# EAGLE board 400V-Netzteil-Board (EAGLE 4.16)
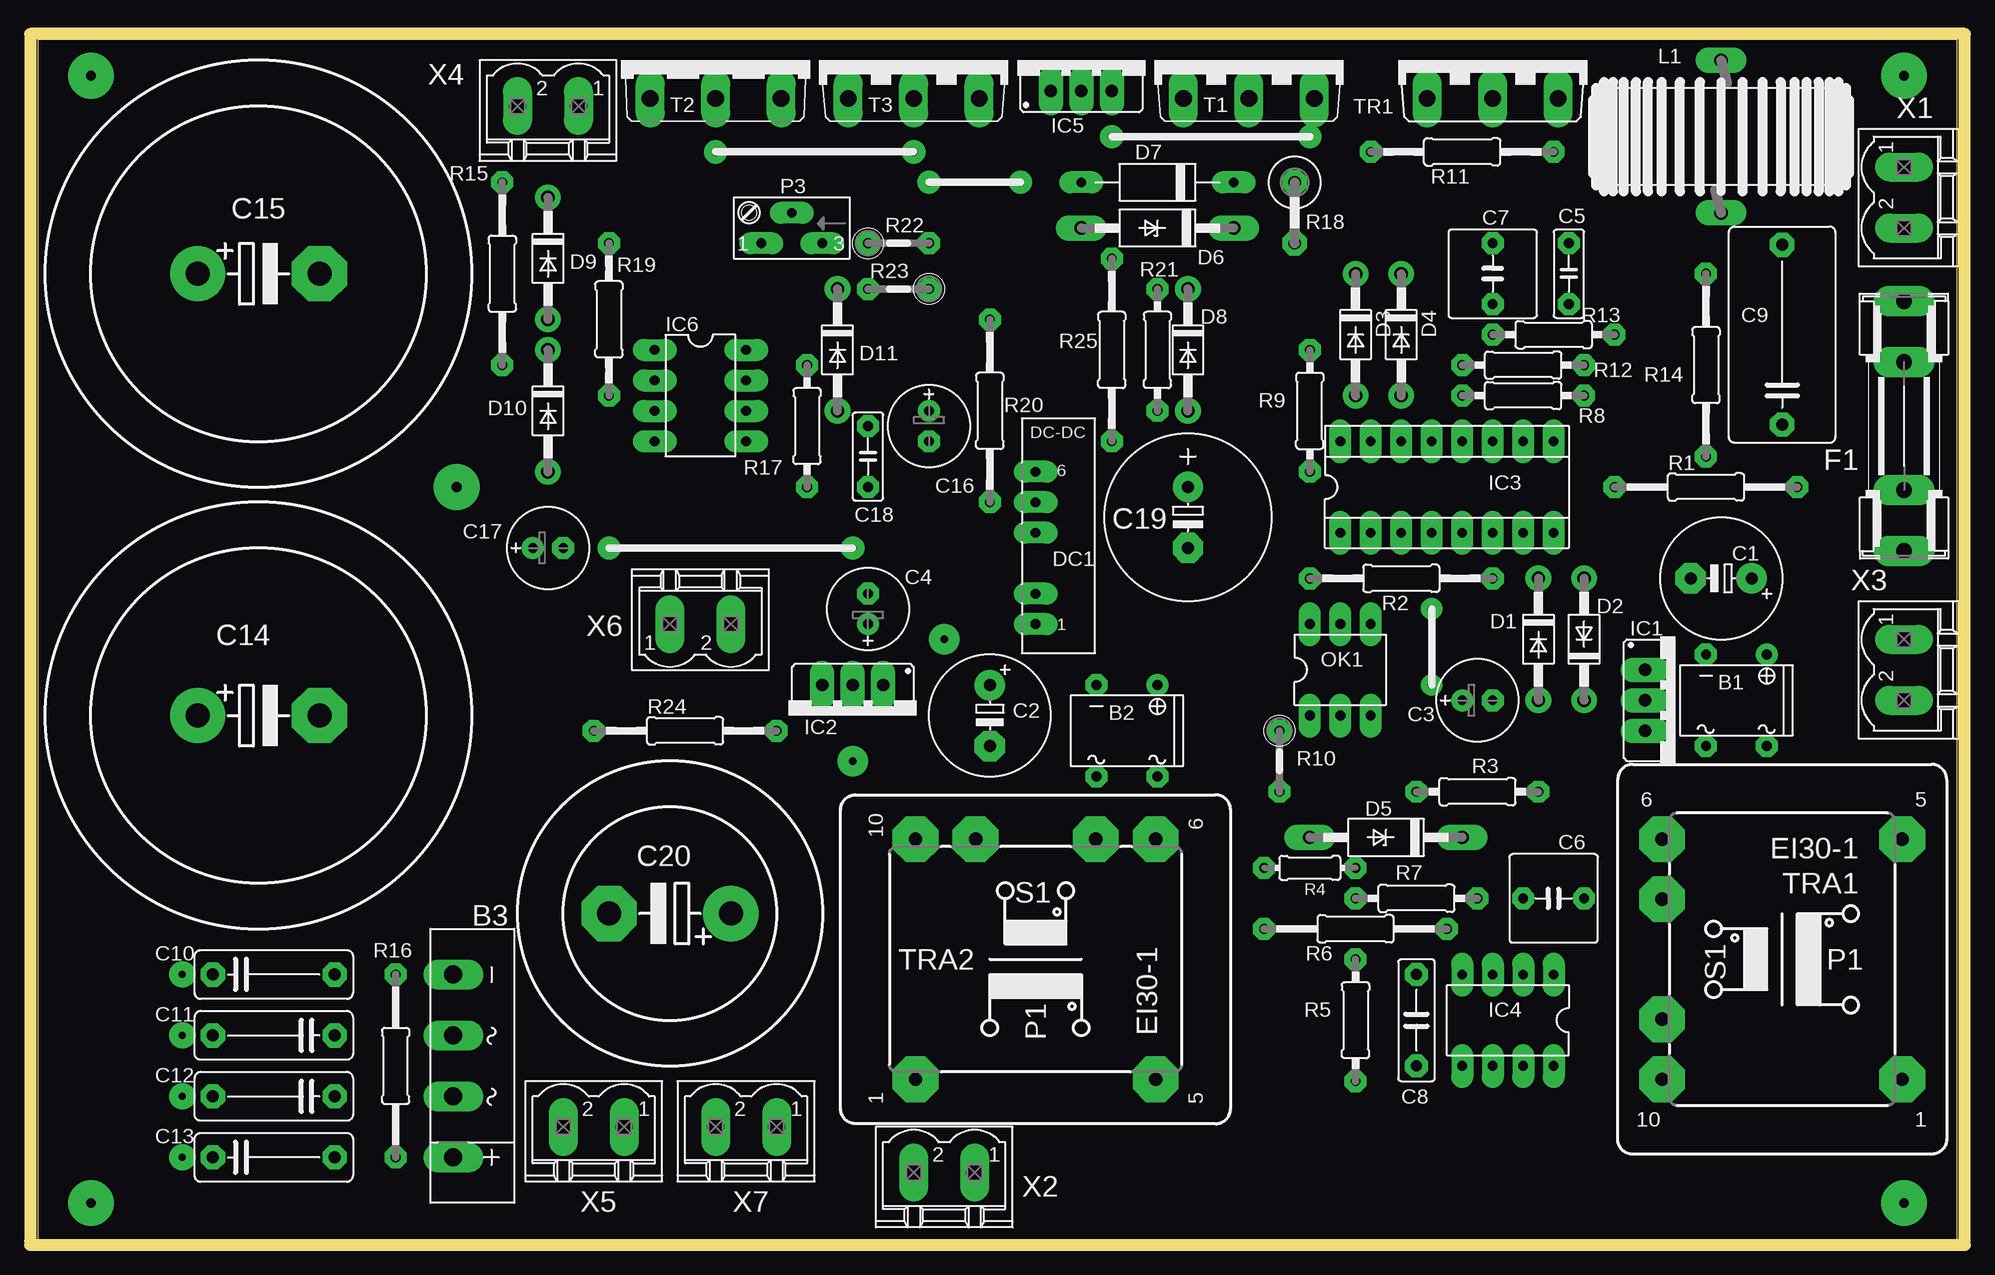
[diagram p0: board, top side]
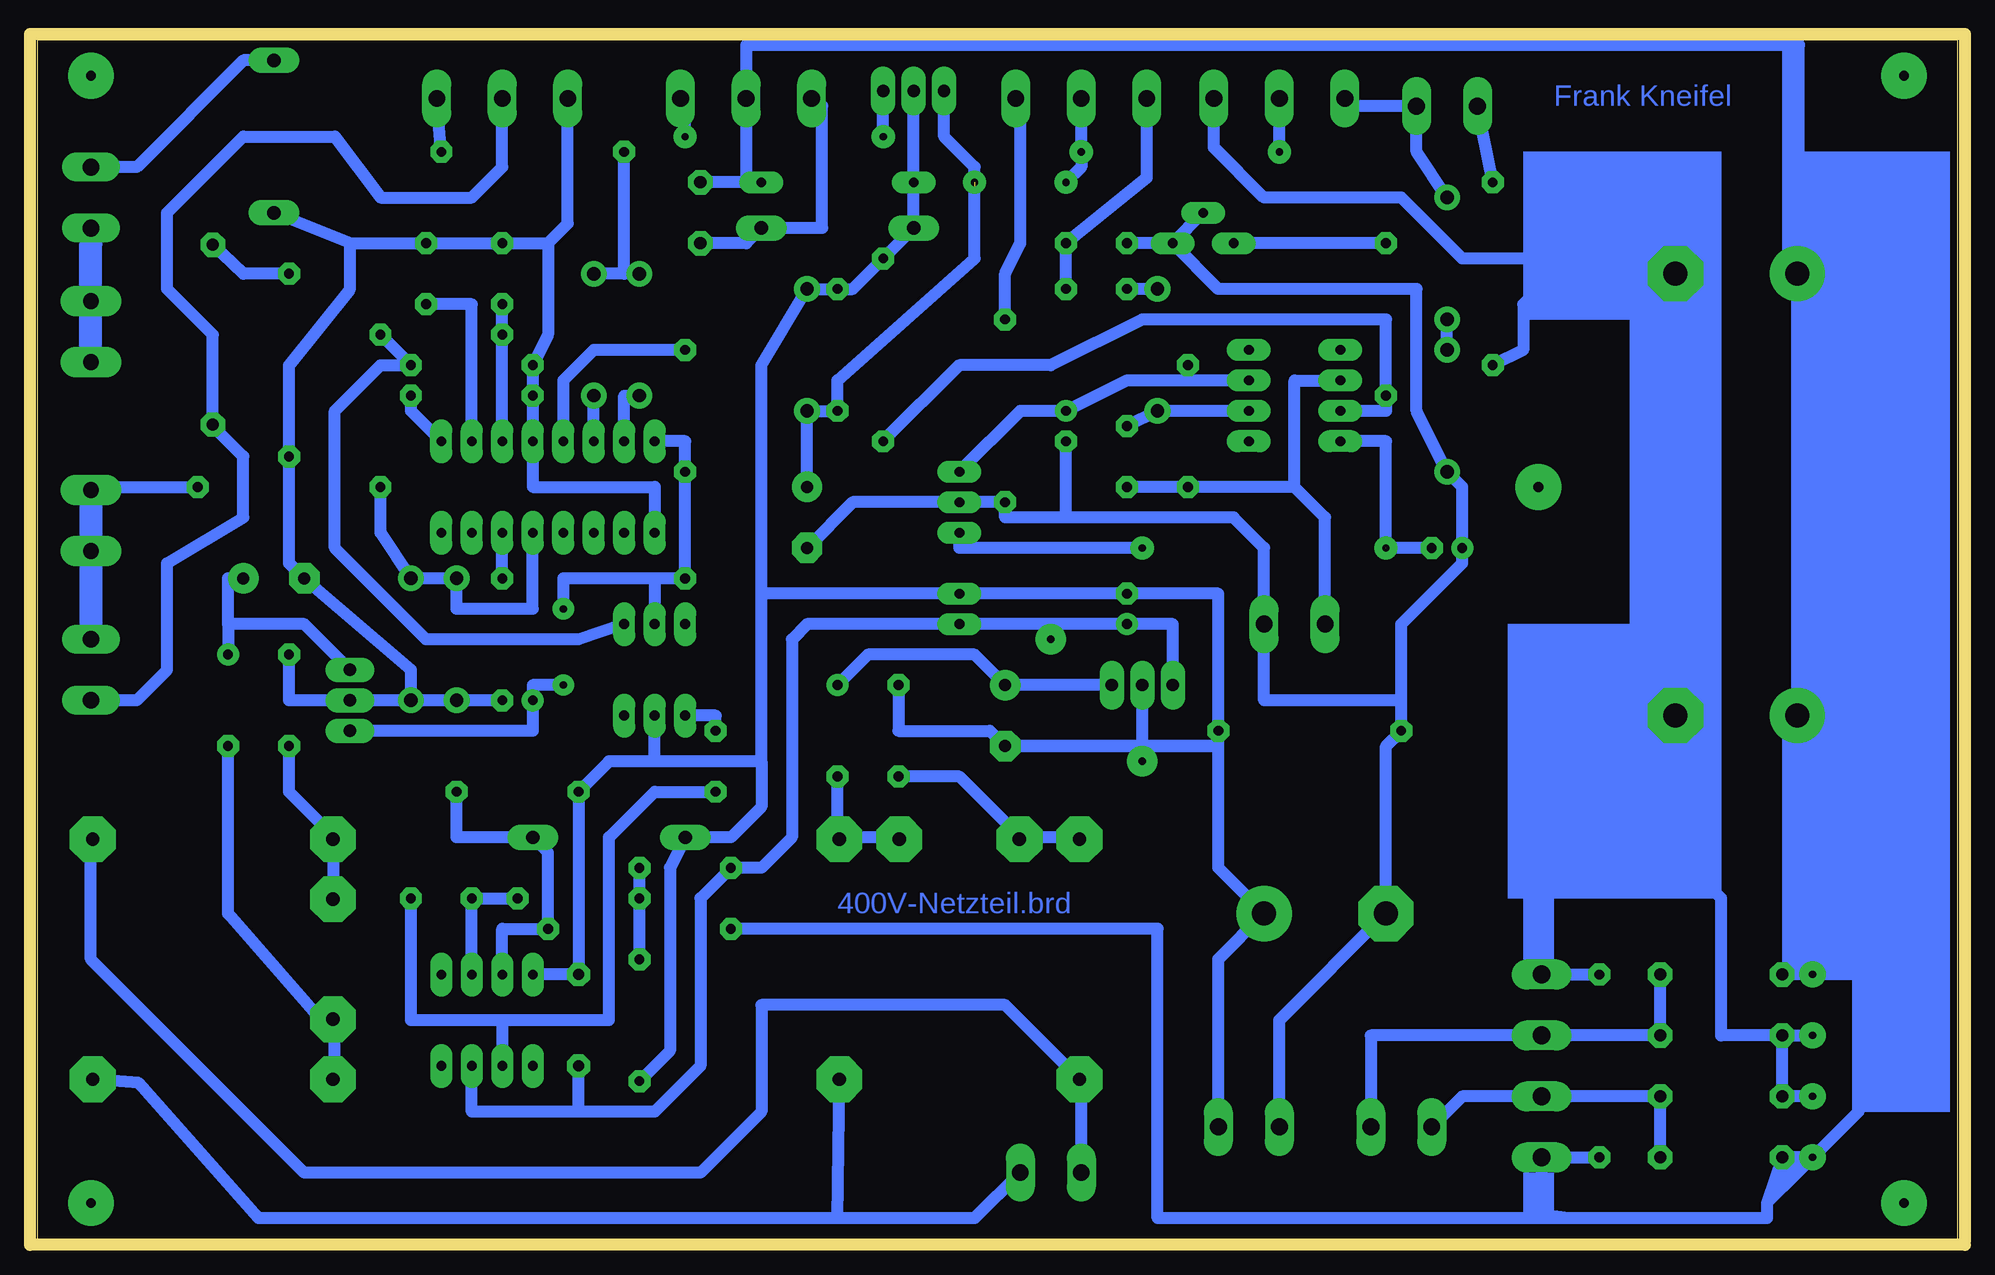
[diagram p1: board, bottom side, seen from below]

Size 161.29 x 100.97 mm. Coordinates in mm from the lower left corner, seen from the top.
Outline: 0,0 161.29,0 161.29,100.97 0,100.97 0,0.32
Outline: 0.64,0.48 160.64,0.48 160.64,100.48 0.64,100.48 0.64,0.48
Copper layers (1*16): Top 0.035mm / dielectric 1.5mm / Bottom 0.035mm
Design rules "default": minimum track width 10mil, minimum drill 24mil, track to track 8mil, track to pad 8mil, pad to pad 8mil, via to via 8mil, smd to smd 8mil, copper to edge 40mil, drill to drill 8mil, minimum pad ring 20mil, minimum via ring 8mil, stop-mask expansion 4mil, vias tented up to drill 0mil, thermal gap 10mil

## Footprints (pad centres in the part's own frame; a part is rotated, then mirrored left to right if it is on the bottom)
B-DIL = drill 0.813 round: + -2.54,-3.81 | drill 0.813 octagon: - 2.54,-3.81; AC1 2.54,3.81; AC2 -2.54,3.81
FBU4 = drill 1.499 long: + 7.62,-1.54; - -7.62,-1.54; AC1 2.54,-1.54; AC2 -2.54,-1.54
E5-10,5 = drill 1.016 pad 2.54 round: + -2.54,0 | drill 1.016 pad 2.54 octagon: - 2.54,0
E2,5-7 = drill 0.813 pad 1.6 round: + -1.27,0 | drill 0.813 pad 1.6 octagon: - 1.27,0
C050-025X075 = drill 0.813 octagon: 1 -2.54,0; 2 2.54,0
C050-075X075 = drill 0.813 octagon: 1 -2.54,0; 2 2.54,0
C075-032X103 = drill 0.914 octagon: 1 -3.81,0; 2 3.81,0
C150-091X182 = drill 1.016 octagon: 1 -7.493,0; 2 7.493,0
C102-043X133 = drill 1.016 octagon: 1 -5.08,0; 2 5.08,0
EB35D = drill 2.007 pad 4.597 round: + -5.08,0 | drill 2.007 pad 4.597 octagon: - 5.08,0
E5-13 = drill 1.016 pad 2.54 round: + -2.54,0 | drill 1.016 pad 2.54 octagon: - 2.54,0
EB25D = drill 2.007 pad 4.597 round: + -5.08,0 | drill 2.007 pad 4.597 octagon: - 5.08,0
DO41-10 = drill 1.118 round: A 5.08,0; C -5.08,0
P1Z12 = drill 1.118 long: A 6.35,0; C -6.35,0
D-12.5 = drill 0.813 long: A 6.35,0; C -6.35,0
NMA = drill 0.813 long: 1 0,6.35; 2 0,3.81; 4 0,-1.27; 5 0,-3.81; 6 0,-6.35
SHK20L = drill 1.321 pad 2.54 long: 1A -10.414,0; 1B -5.334,0; 2A 10.414,0; 2B 5.334,0
78XXS = drill 1.016 long: GND 0,-2.54; IN -2.54,-2.54; OUT 2.54,-2.54
SOCKED-16 = drill 0.813 long: 1 -8.89,-3.81; 2 -6.35,-3.81; 3 -3.81,-3.81; 4 -1.27,-3.81; 5 1.27,-3.81; 6 3.81,-3.81; 7 6.35,-3.81; 8 8.89,-3.81; 9 8.89,3.81; 10 6.35,3.81; 11 3.81,3.81; 12 1.27,3.81; 13 -1.27,3.81; 14 -3.81,3.81; 15 -6.35,3.81; 16 -8.89,3.81
DIL08 = drill 0.813 long: 1 -3.81,-3.81; 2 -1.27,-3.81; 3 1.27,-3.81; 4 3.81,-3.81; 5 3.81,3.81; 6 1.27,3.81; 7 -1.27,3.81; 8 -3.81,3.81
317TS = drill 1.016 long: 1 -2.54,-2.54; 2 0,-2.54; 3 2.54,-2.54
SFT1030 = drill 1.118 long: 1 -6.35,0; 2 6.35,0
DIL06 = drill 0.813 long: 1 -2.54,-3.81; 2 0,-3.81; 3 2.54,-3.81; 4 2.54,3.81; 5 0,3.81; 6 -2.54,3.81
S64Y = drill 0.813 long: A 2.54,1.27; E -2.54,1.27; S 0,-1.27
0207/15 = drill 0.813 octagon: 1 -7.62,0; 2 7.62,0
0207/10 = drill 0.813 octagon: 1 -5.08,0; 2 5.08,0
0204/7 = drill 0.813 octagon: 1 -3.81,0; 2 3.81,0
0207/5V = drill 0.813 octagon: 1 -2.54,0; 2 2.54,0
0414V = drill 1.016 octagon: 1 -2.54,0; 2 2.54,0
0207/12 = drill 0.813 octagon: 1 -6.35,0; 2 6.35,0
TO218V = drill 1.397 long: 1 -5.461,-3.175; 2 0,-3.175; 3 5.461,-3.175
TOP3V = drill 1.397 long: B -5.461,-3.175; C 0,-3.175; E 5.461,-3.175
TO218DS = drill 1.397 long: A1 -5.461,-3.175; A2 0,-3.175; G 5.461,-3.175
EI30-1 = drill 1.118 pad 3.81 octagon: 1 -10.008,10.008; 5 -10.008,-10.008; 6 10.008,-10.008; 7 10.008,-5.004; 9 10.008,5.004; 10 10.008,10.008
MSTBV2 = drill 1.397 long: 1 -2.54,0; 2 2.54,0

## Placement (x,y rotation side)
B1  B250C800DIP  [B-DIL]  142.24,45.4 180 top
B2  B250C800DIP  [B-DIL]  91.44,42.86 180 top
B3  KBU8M  [FBU4]  36.83,14.92 270 top
C1  470µ/35V  [E5-10,5]  140.97,55.56 180 top
C2  470µ/35V  [E5-10,5]  80.01,44.13 270 top
C3  47µF/50V  [E2,5-7]  120.65,45.4 0 top
C4  22µ/25V  [E2,5-7]  69.85,53.02 90 top
C5  33n  [C050-025X075]  128.27,80.96 90 top
C6  4,7µ  [C050-075X075]  127,28.89 0 top
C7  4,7µ  [C050-075X075]  121.92,80.96 270 top
C8  100n  [C075-032X103]  115.57,18.73 90 top
C9  100n/630V  [C150-091X182]  146.05,75.88 90 top
C10  2,2n  [C102-043X133]  20.32,22.54 0 top
C11  2,2n  [C102-043X133]  20.32,17.46 180 top
C12  2,2n  [C102-043X133]  20.32,7.3 0 top
C13  2,2n  [C102-043X133]  20.32,12.38 180 top
C14  470µF/450V  [EB35D]  19.05,44.13 0 top
C15  470µF/450V  [EB35D]  19.05,80.96 0 top
C16  22µ/25V  [E2,5-7]  74.93,68.26 270 top
C17  22µ/25V  [E2,5-7]  43.18,58.1 0 top
C18  100n  [C050-025X075]  69.85,65.72 90 top
C19  10µF/450V  [E5-13]  96.52,60.64 270 top
C20  100µF/450V  [EB25D]  53.34,27.62 180 top
D1  1N4007  [DO41-10]  125.73,50.48 270 top
D2  1N4007  [DO41-10]  129.54,50.48 90 top
D3  1N4007  [DO41-10]  110.49,75.88 270 top
D4  1N4007  [DO41-10]  114.3,75.88 270 top
D5  12V  [P1Z12]  113.03,33.97 180 top
D6  10V  [P1Z12]  93.98,84.77 180 top
D7  1N4007  [D-12.5]  93.98,88.58 180 top
D8  1N4007  [DO41-10]  96.52,74.61 270 top
D9  1N4007  [DO41-10]  43.18,82.23 270 top
D10  1N4007  [DO41-10]  43.18,69.53 270 top
D11  1N4007  [DO41-10]  67.31,74.61 270 top
DC1  [NMA]  83.82,58.1 180 top
F1  T1,6A  [SHK20L]  156.21,68.26 90 top
IC1  µA7815  [78XXS]  137.16,45.4 270 top
IC2  µA7815  [78XXS]  68.58,44.13 180 top
IC3  TCA785  [SOCKED-16]  118.11,63.18 0 top
IC4  TL061  [DIL08]  123.19,18.73 180 top
IC5  LM317  [317TS]  87.63,98.74 0 top
IC6  TL081  [DIL08]  55.88,70.8 270 top
L1  100µ  [SFT1030]  140.97,92.39 90 top
OK1  CNY17-2  [DIL06]  109.22,47.94 0 top
P3  2k  [S64Y]  63.5,84.77 180 top
R1  220k/2W  [0207/15]  139.7,63.18 0 top
R2  10k  [0207/15]  114.3,55.56 180 top
R3  100k  [0207/10]  120.65,37.78 0 top
R4  100k  [0204/7]  106.68,31.43 180 top
R5  47k  [0207/10]  110.49,18.73 90 top
R6  150k  [0207/15]  110.49,26.35 180 top
R7  1k  [0207/10]  115.57,28.89 0 top
R8  100k  [0207/10]  124.46,70.8 0 top
R9  1M  [0207/10]  106.68,69.53 270 top
R10  1,2k  [0207/5V]  104.14,40.32 270 top
R11  150/2W  [0207/15]  119.38,91.12 0 top
R12  4,7k  [0207/10]  124.46,73.34 0 top
R13  2,2k  [0207/10]  127,75.88 180 top
R14  220/2W  [0207/15]  139.7,73.34 90 top
R15  1/2W (*3)  [0207/15]  39.37,80.96 270 top
R16  220k/2W  [0207/15]  30.48,14.92 270 top
R17  1k  [0207/10]  64.77,68.26 90 top
R18  100k/2W  [0414V]  105.41,86.04 270 top
R19  9,1k  [0207/12]  48.26,77.15 90 top
R20  100/2W  [0207/15]  80.01,69.53 90 top
R21  240  [0207/10]  93.98,74.61 90 top
R22  100k  [0207/5V]  72.39,83.5 0 top
R23  10k  [0207/5V]  72.39,79.69 180 top
R24  180k/2W  [0207/15]  54.61,42.86 0 top
R25  680k/2W (*4)  [0207/15]  90.17,74.61 90 top
T1  IRF840  [TO218V]  101.6,98.74 0 top
T2  BUX85  [TOP3V]  57.15,98.74 0 top
T3  IRF840  [TO218V]  73.66,98.74 0 top
TR1  BTB24-600  [TO218DS]  121.92,98.74 0 top
TRA1  [EI30-1]  146.05,23.81 180 top
TRA2  [EI30-1]  83.82,23.81 90 top
X1  MST2V  [MSTBV2]  156.21,87.31 270 top
X2  MST2V  [MSTBV2]  76.2,6.03 180 top
X3  MST2V  [MSTBV2]  156.21,47.94 270 top
X4  MST2V  [MSTBV2]  43.18,94.93 180 top
X5  MST2V  [MSTBV2]  46.99,9.84 180 top
X6  MST2V  [MSTBV2]  55.88,51.75 0 top
X7  MST2V  [MSTBV2]  59.69,9.84 180 top

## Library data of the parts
B1-B3 = rectifier
C1-C20 R1-R25 = rcl
D1-D11 = diode
DC1 = dc-dc-converter
F1 = fuse
IC1 IC2 IC5 = v-reg
IC3 = ic-package
IC4 IC6 = linear
L1 = inductors
OK1 = optocoupler
P3 = pot
T1 T3 = transistor-fet
T2 = transistor
TR1 = triac
TRA1 TRA2 = trafo
X1-X7 = con-phoenix-508

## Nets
N$1: B1.- C1.- C3.- C5.2 C7.1 D1.A D2.C IC1.GND IC3.1 IC3.12 L1.1 R8.1 R12.1 R14.1 TR1.A1
N$2: C3.+ IC1.OUT IC3.16 OK1.5 R2.2 R9.2
N$3: D3.A IC3.15
N$4: D4.A IC3.14
N$5: D3.C D4.C R11.1
N$6: C9.2 R14.2
N$7: C7.2 IC3.11 R13.2
N$8: D1.C D2.A IC3.5 R1.1
N$9: C9.1 TR1.A2 X3.2
N$10: R11.2 TR1.G
N$11: F1.1A R1.2 X3.1
N$12: IC3.6 R2.1
N$13: IC3.13 R9.1
N$14: B1.+ C1.+ IC1.IN
N$15: IC3.9 R8.2
N$16: B2.- C2.- C4.- C8.2 C20.+ D5.A D6.A D7.A D8.C DC1.2 IC2.GND IC4.4 IC5.2 OK1.2 R3.1 R5.1 R21.2 R24.2 R25.2 X7.1
N$17: C5.1 IC3.10
N$18: C6.1 IC4.2 R7.2
N$19: C6.2 IC4.6 R10.2
N$20: B2.AC1 TRA2.9
N$21: B1.AC1 TRA1.7
N$22: F1.2A X1.2
N$23: OK1.4 R12.2 R13.1
N$24: OK1.1 R10.1
N$25: R4.1 R5.2 R7.1
N$26: D5.C IC4.3 R3.2 R6.1
N$27: B2.+ C2.+ IC2.IN
N$28: C4.+ C8.1 DC1.1 IC2.OUT IC4.7 R4.2
N$29: B1.AC2 TRA1.9
N$30: C17.- DC1.4 IC6.4
N$31: B2.AC2 TRA2.7
N$32: D6.C R18.2 T1.1
N$33: B3.AC2 C10.2 C11.1 X5.1
N$34: IC5.3 T1.3
N$35: B3.+ C10.1 C12.1 C14.+ C15.+ D7.C R6.2 R16.2 R18.1 T1.2
N$36: R20.2 T3.3
N$37: TRA1.5 TRA2.1 X2.2
N$38: B3.AC1 C12.2 C13.1 X5.2
N$39: C16.- C17.+ C19.- C20.- D10.A DC1.5 P3.E P3.S R20.1 R22.1 R24.1 X6.2 X7.2
N$40: B3.- C11.2 C13.2 C14.- C15.- R15.2 R16.1 T2.E
N$41: R15.1 X4.2
N$42: D9.A D10.C
N$43: D9.C T2.B X4.1
N$44: C19.+ D8.A IC5.1 R21.1 T2.C T3.2
N$45: R22.2 R23.1 T3.1
N$46: C18.2 D11.A IC6.6
N$47: D11.C R23.2
N$48: C18.1 IC6.2 R17.1 X6.1
N$49: P3.A R19.2
N$50: IC6.3 R19.1 R25.1
N$51: C16.+ DC1.6 IC6.7 R17.2
N$52: TRA1.1 TRA2.5 X2.1
N$59: L1.2 X1.1

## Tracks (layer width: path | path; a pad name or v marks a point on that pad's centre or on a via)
N$1
  Bottom 0.406: D2.C IC1.GND
  Bottom 1.016: B1.- 139.7,45.4 IC1.GND D2.C | D2.C D1.A C3.- | IC3.1 109.22,63.18 119.38,63.18 IC3.12 R8.1 R12.1 118.11,75.88 118.11,83.5 | D2.C 129.54,47.94 C1.- 139.7,56.83 R14.1 139.7,73.34 134.62,79.69 134.62,83.5 | 134.62,83.5 C7.1 118.11,83.5 | TR1.A1 116.46,85.15 118.11,83.5 | 134.62,83.5 L1.1 | 134.62,83.5 C5.2
N$2  (via drill 0.6 pad 1.78)
  Top 0.61: v116.84,53.02 v116.84,46.67
  Bottom 1.016: IC3.16 106.68,66.99 R9.2 R2.2 109.22,55.56 | v116.84,46.67 119.38,46.67 C3.+ 119.38,42.86 IC1.OUT | 109.22,55.56 OK1.5 | 109.22,55.56 116.84,55.56 v116.84,53.02
N$3
  Bottom 1.016: D3.A 111.76,70.8 IC3.15
N$4
  Bottom 0.406: IC3.14 D4.A
  Bottom 1.016: IC3.14 D4.A
N$5
  Bottom 1.016: 111.76,80.96 R11.1 | D3.C 111.76,80.96 | 111.76,80.96 D4.C
N$6
  Bottom 1.016: R14.2 143.51,80.96 C9.2 146.05,83.5
N$7
  Bottom 1.016: IC3.11 R13.2 C7.2
N$8
  Bottom 0.406: D1.C D2.A
  Bottom 1.016: IC3.5 119.38,53.02 125.73,53.02 D1.C D2.A 132.08,59.37 R1.1
N$9
  Bottom 1.016: 146.05,68.26 143.51,65.72 143.51,60.64 149.86,56.83 149.86,47.94 152.4,45.4 X3.2 | 146.05,68.26 C9.1 | 146.05,68.26 146.05,75.88 149.86,79.69 149.86,86.04 143.51,92.39 135.89,92.39 132.08,87.31 124.46,87.31 121.92,89.85 TR1.A2
N$10
  Bottom 1.016: R11.2 TR1.G
N$11
  Bottom 1.016: 156.21,63.18 R1.2 | 156.21,63.18 156.21,61.91 F1.1A 156.21,51.75 | X3.1 156.21,63.18
  Bottom 1.93: 156.21,61.91 156.21,51.75
N$12
  Bottom 1.016: R2.1 IC3.6
N$13
  Bottom 1.016: IC3.13 116.84,72.07 114.3,74.61 R9.1
N$14
  Bottom 1.016: IC1.IN 138.43,51.75 144.78,51.75 | 144.78,51.75 B1.+ | C1.+ 144.78,55.56 144.78,51.75
N$15
  Bottom 1.016: R8.2 129.54,69.53 IC3.9
N$16
  Bottom 0.254: 62.23,54.29 C4.-
  Bottom 0.406: 100.33,40.32 100.33,54.29 100.33,70.8
  Bottom 1.016: 68.58,41.59 C2.- | 68.58,41.59 IC2.GND | 62.23,54.29 R24.2 62.23,41.59 | 100.33,54.29 DC1.2 62.23,54.29 | 100.33,40.32 100.33,70.8 100.33,73.34 D8.C R21.2 92.71,79.69 R25.2 D6.A D7.A IC5.2 | 100.33,40.32 100.33,36.51 102.87,33.97 D5.A 107.95,31.43 107.95,16.19 R5.1 | IC4.4 C8.2 R3.1 113.03,40.32 109.22,40.32 | 109.22,40.32 OK1.2 | 100.33,40.32 109.22,40.32 | 62.23,41.59 62.23,31.43 C20.+ 62.23,23.81 X7.1 | 62.23,41.59 68.58,41.59 | B2.- 88.9,42.86 81.28,42.86 C2.- | C2.- 62.23,41.59 | 62.23,41.59 62.23,54.29
N$17
  Bottom 1.016: IC3.10 124.46,78.42 C5.1
N$18
  Bottom 0.406: R7.2 C6.1 IC4.2
  Bottom 1.016: R7.2 C6.1 IC4.2
N$19
  Bottom 1.016: 121.92,18.73 113.03,18.73 113.03,33.97 109.22,37.78 R10.2 | 121.92,18.73 129.54,18.73 C6.2 | 121.92,18.73 IC4.6
N$20
  Bottom 0.406: 78.74,33.97 78.82,33.9 TRA2.9
  Bottom 1.016: 73.66,33.97 78.74,33.97 | 78.74,33.97 80.01,33.97 | 78.74,33.97 83.82,39.05 B2.AC1
N$21
  Bottom 0.406: TRA1.7 135.97,27.55
  Bottom 1.016: B1.AC1 139.7,37.78 135.89,33.97 135.97,33.9 135.97,27.55
N$22
  Bottom 1.016: 156.21,73.34 F1.2A 156.21,83.5 X1.2
  Bottom 1.93: 156.21,73.34 156.21,83.5
N$23
  Bottom 1.016: OK1.4 115.57,50.48 128.27,50.48 135.89,58.1 135.89,69.53 132.08,73.34 R12.2 R13.1
N$24
  Bottom 1.016: OK1.1 104.14,44.13 R10.1
N$25
  Bottom 1.016: R4.1 R7.1 R5.2
N$26
  Bottom 1.016: IC4.3 121.92,26.35 R6.1 118.11,32.7 D5.C 125.73,33.97 R3.2
N$27
  Bottom 0.406: IC2.IN C2.+
  Bottom 1.016: IC2.IN C2.+ 82.55,49.21 91.44,49.21 B2.+
N$28
  Bottom 1.016: IC2.OUT 66.04,51.75 C4.+ DC1.1 96.52,51.75 97.79,50.48 97.79,33.97 100.33,31.43 R4.2 105.41,28.89 105.41,14.92 109.22,11.11 115.57,11.11 | IC4.7 124.46,11.11 115.57,11.11 | 115.57,11.11 C8.1
N$29
  Bottom 0.406: 135.89,17.46 135.97,17.54 | 135.97,17.54 TRA1.9 | 135.97,17.54 144.78,27.62
  Bottom 1.016: B1.AC2 144.78,27.62 135.89,17.46 135.89,13.65
N$30  (via drill 0.6 pad 1.93)  (1 unrouted)
  Top 0.61: 48.26,58.1 52.07,58.1 v68.58,58.1
  Bottom 0.61: 48.26,58.1 48.26,57.79
  Bottom 1.016: IC6.4 48.26,66.99 48.26,58.1 C17.- | DC1.4 83.82,58.1 v68.58,58.1
N$31
  Bottom 0.406: 88.9,33.97 88.82,33.9 TRA2.7
  Bottom 1.016: B2.AC2 93.98,33.97 88.9,33.97
N$32
  Bottom 1.016: T1.1 95.88,95.57 95.25,94.93 95.25,84.77 D6.C 101.6,83.5 R18.2
N$33
  Bottom 1.016: C10.2 C11.1 B3.AC2 49.53,17.46 X5.1
N$34  (via drill 0.6 pad 1.93)
  Top 0.61: 106.68,92.39 v90.17,92.39
  Bottom 1.016: v90.17,92.39 IC5.3 | T1.3 107.06,95.31 106.68,93.66 106.68,92.39 T1.3
N$35  (via drill 0.6 pad 2.18)
  Bottom 0.254: 11.43,42.86 12.7,42.86
  Bottom 0.406: 13.97,100.01 15.24,100.01
  Bottom 1.016: 15.24,100.01 17.78,100.01 | R6.2 67.31,26.35 67.31,2.22 33.02,2.22 | 33.02,2.22 16.51,2.22 16.51,3.49 | 13.97,100.01 17.78,100.01 | B3.+ 35.29,2.49 33.02,2.22 | 8.89,22.54 8.89,11.11 12.7,7.3 | 8.89,22.54 8.89,42.86 | 8.89,22.54 v12.7,22.54 C10.1 | 17.78,100.01 101.6,100.01 T1.2 101.6,93.66 101.6,88.58 | 101.6,88.58 D7.C | 101.6,88.58 R18.1 | B3.+ 35.56,7.3 | B3.+ R16.2 | 13.97,82.23 C15.+ C14.+ 12.7,44.13 | 12.7,7.3 13.97,6.03 | 12.7,7.3 13.97,7.3 | 13.97,7.3 C12.1 16.51,3.49 | 13.97,7.3 16.51,3.49 | 13.97,6.03 13.97,7.3 | 13.97,6.03 16.51,3.49
  Bottom 1.27: 13.97,82.23 13.97,100.01 | 12.7,44.13 11.43,42.86 8.89,42.86
N$36
  Bottom 1.016: R20.2 80.01,80.96 78.74,83.5 78.74,94.93 79.12,95.31 T3.3
N$37
  Bottom 1.016: TRA1.5 156.21,32.7 156.21,23.81 138.43,6.03 105.41,6.03 100.33,11.11 100.33,20 80.01,20 TRA2.1 73.66,13.65 X2.2
N$38
  Bottom 1.016: X5.2 41.91,12.38 B3.AC1 C13.1 C12.2
N$39
  Bottom 1.016: 46.99,45.4 58.42,45.4 X6.2 58.42,58.1 60.96,60.64 74.93,60.64 | 74.93,60.64 80.01,60.64 R20.1 DC1.5 92.71,61.91 C19.- | 74.93,60.64 C16.- | P3.E 62.23,79.69 45.72,79.69 45.72,69.53 D10.A 41.91,63.18 C17.+ 41.91,56.83 46.99,51.75 46.99,45.4 | P3.E P3.S | P3.E R22.1 | 46.99,45.4 R24.1 48.26,41.59 C20.- 57.15,18.73 X7.2
N$40  (via drill 0.6 pad 2.18)
  Bottom 0.406: 33.02,80.96 34.29,80.96 | 24.13,47.94 24.13,56.83 | 24.13,61.91 24.13,63.18
  Bottom 1.016: C11.2 C13.2 v12.7,12.38 | C11.2 v12.7,17.46 | T2.E 62.61,91.5 58.42,87.31 46.99,87.31 41.91,82.23 34.29,82.23 33.02,80.96 C15.- 24.13,63.18 | R15.2 36.83,74.61 36.83,78.42 34.29,80.96 | 34.2,48.16 34.29,47.94 35.56,44.13 35.56,22.54 B3.- | B3.- R16.1 B3.- | C11.2 20.32,17.46 20.32,28.89 24.13,32.7 C14.-
  Bottom 1.27: C14.- 24.13,46.67 24.13,47.94 22.86,49.21
  Bottom 1.422: 24.13,61.91 24.13,56.83 24.13,63.18
  Bottom 1.93: 21.59,47.94 C14.- 34.2,48.16 36.83,49.21 | 22.86,49.21 22.86,46.67 | 24.13,47.94 30.48,47.94 | 24.13,46.67 27.94,46.67
N$41
  Bottom 1.016: R15.1 X4.2
N$42
  Bottom 0.406: D10.C D9.A
  Bottom 1.016: D10.C D9.A
N$43
  Bottom 1.016: D9.C 45.72,91.12 X4.1 | X4.1 45.72,96.2 | T2.B 51.44,95.57 50.8,94.93 X4.1
N$44  (via drill 0.6, 0.6 pad 1.93)  (1 unrouted)
  Top 0.61: v57.15,91.12 v73.66,91.12 | 74.61,88.58 v74.93,88.58 80.01,88.58 82.55,88.58
  Bottom 0.406: D8.A R21.1
  Bottom 1.016: C19.+ D8.A R21.1 93.98,72.07 82.55,82.23 82.55,88.26 82.55,89.85 85.09,92.39 IC5.1 | T3.2 v73.66,91.12 73.66,89.85 v74.93,88.58 | v57.15,91.12 T2.C
N$45
  Bottom 1.016: T3.1 68.2,88.96 R22.2 R23.1
N$46
  Bottom 1.016: IC6.6 D11.A C18.2
N$47
  Bottom 1.016: D11.C R23.2
N$48
  Bottom 1.016: IC6.2 55.88,72.07 55.88,63.18 | 55.88,63.18 53.34,60.64 X6.1 | C18.1 R17.1 55.88,63.18
N$49
  Bottom 1.016: R19.2 P3.A
N$50
  Bottom 1.016: IC6.3 48.26,69.53 R19.1 48.26,77.15 68.58,77.15 76.2,73.34 83.82,73.34 R25.1
N$51
  Bottom 1.016: DC1.6 78.74,69.53 C16.+ 69.85,72.07 64.77,72.07 | IC6.7 64.77,72.07 | 64.77,72.07 R17.2
N$52
  Bottom 1.016: TRA1.1 152.25,13.5 142.24,2.22 93.98,2.22 | 93.98,2.22 82.55,2.22 X2.1 | 93.98,2.22 TRA2.5
N$53  (via drill 0.6 pad 1.93)
  other vias: 48.26,58.1
N$54  (via drill 0.8 pad 3.81)
  other vias: 5.08,97.47
N$59
  Bottom 1.016: L1.2 143.51,98.74 152.4,89.85 X1.1
N$60  (via drill 0.6 pad 2.54)
  other vias: 76.2,50.48
N$61  (via drill 0.6 pad 1.93)
  other vias: 74.93,88.58
N$62  (via drill 0.6 pad 2.54)
  other vias: 68.58,40.32
N$63  (via drill 0.8 pad 3.81)
  other vias: 5.08,3.49
N$64  (via drill 0.8 pad 3.81)
  other vias: 156.21,97.47
N$65  (via drill 0.8 pad 3.81)
  other vias: 35.56,63.18
N$66  (via drill 0.6 pad 1.78)
  other vias: 116.84,53.02
N$67  (via drill 0.8 pad 3.81)
  other vias: 156.21,3.49
N$68  (via drill 0.6 pad 1.93)
  other vias: 82.55,88.58
N$69  (via drill 0.6 pad 1.93)
  other vias: 106.68,92.39
N$71  (via drill 0.6 pad 2.18)
  other vias: 12.7,7.3
(copper drawn outside any net)
  shapes: Bottom area x28

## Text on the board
Bottom: Frank Kneifel | 400V-Netzteil.brd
